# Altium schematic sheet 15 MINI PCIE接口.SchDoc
size 297 x 209 mm
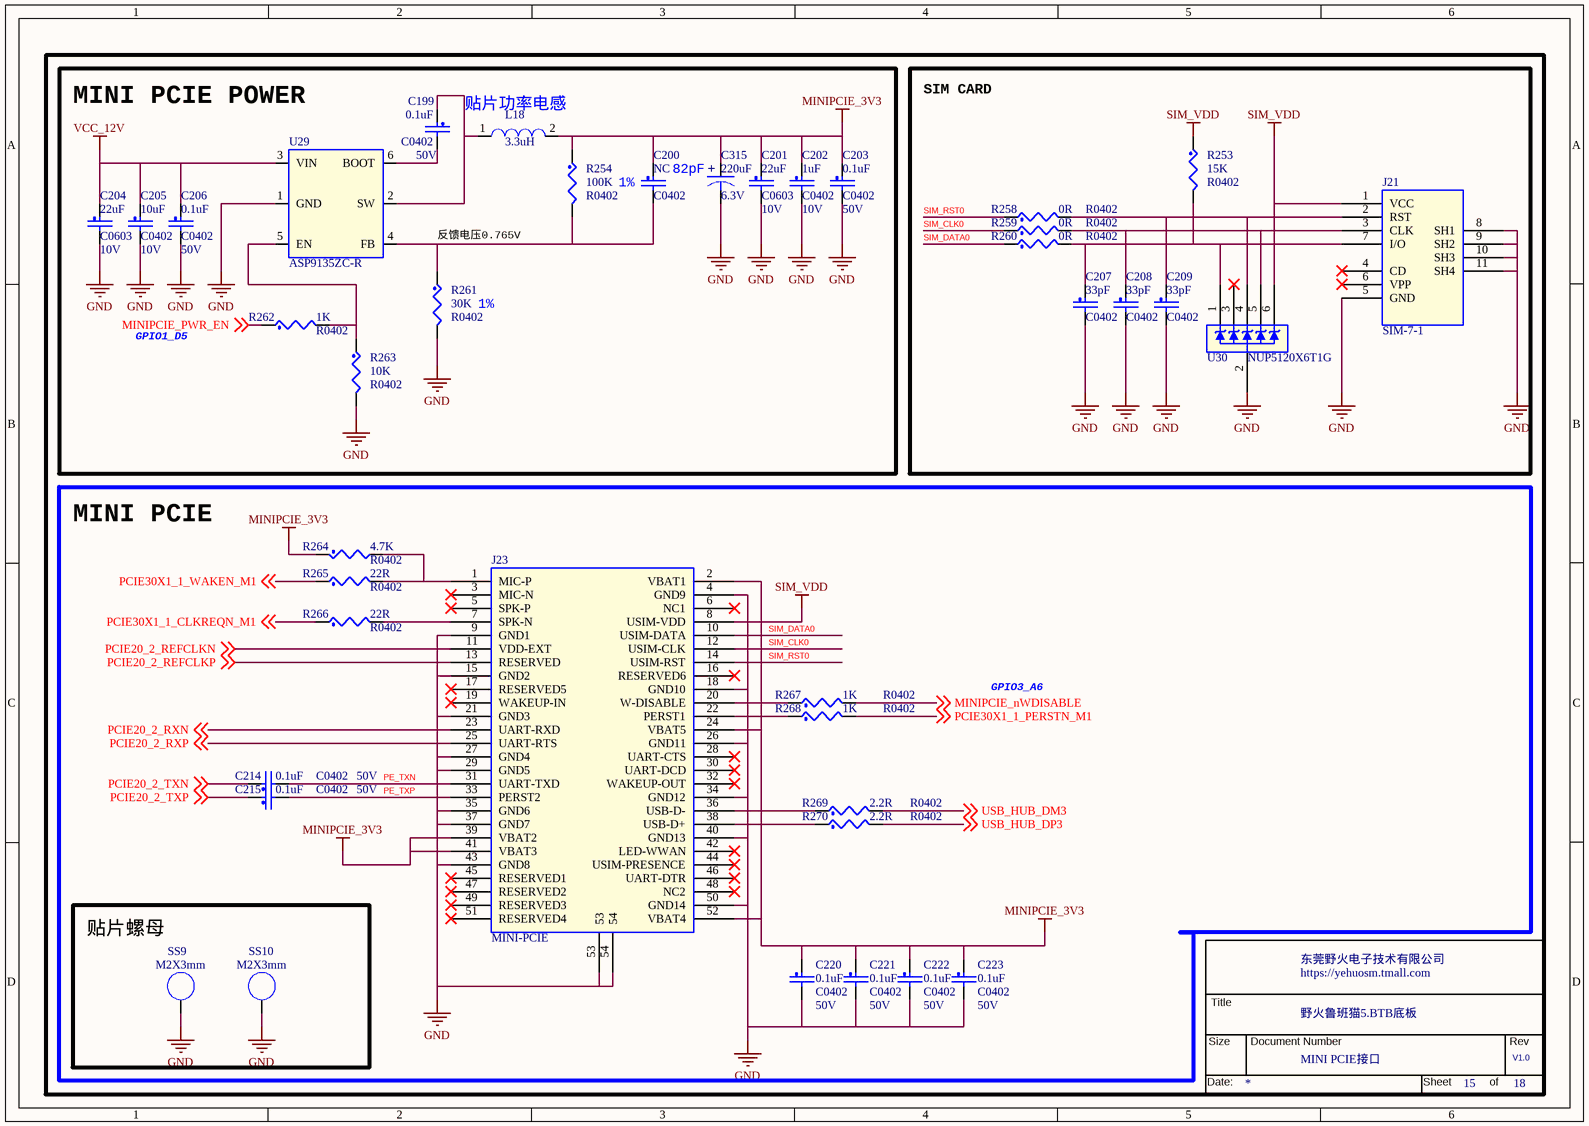
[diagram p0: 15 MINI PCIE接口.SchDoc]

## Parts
*  Doc: MINI PCIE接口  RevCode: V1.0  Title: 野火鲁班猫5.BTB底板  OrgName: 东莞野火电子技术有限公司  Page Number: 15  Page Count: 18  (hidden comment: TitleBlock_YHSCH)  (graphical)
C199  0.1uF  Voltage: 50V  [C0402]
C200  NC  [C0402]
C201  22uF  Voltage: 10V  [C0603]
C202  1uF  Voltage: 10V  [C0402]
C203  0.1uF  Voltage: 50V  [C0402]
C204  22uF  Voltage: 10V  [C0603]
C205  10uF  Voltage: 10V  [C0402]
C206  0.1uF  Voltage: 50V  [C0402]
C207  33pF  [C0402]
C208  33pF  [C0402]
C209  33pF  [C0402]
C214  0.1uF  Voltage: 50V  [C0402]
C215  0.1uF  Voltage: 50V  [C0402]
C220  0.1uF  Voltage: 50V  [C0402]
C221  0.1uF  Voltage: 50V  [C0402]
C222  0.1uF  Voltage: 50V  [C0402]
C223  0.1uF  Voltage: 50V  [C0402]
C315  220uF  Voltage: 6.3V  [T2012]
J21  SIM-7-1  [nano_sim]
J23  MINI-PCIE  [pcie_52p]
L18  3.3uH  [l4520]
R253  15K  [R0402]
R254  100K  [R0402]
R258  0R  [R0402]
R259  0R  [R0402]
R260  0R  [R0402]
R261  30K  [R0402]
R262  1K  [R0402]
R263  10K  [R0402]
R264  4.7K  [R0402]
R265  22R  [R0402]
R266  22R  [R0402]
R267  1K  [R0402]
R268  1K  [R0402]
R269  2.2R  [R0402]
R270  2.2R  [R0402]
SS9  M2X3mm  [t3r2-5r2_topsmt]
SS10  M2X3mm  [t3r2-5r2_topsmt]
U29  ASP9135ZC-R  [SOT23_6]
U30  NUP5120X6T1G  [SOT563]

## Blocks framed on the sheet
MINI PCIE POWER: C199-C206 C315 L18 R254 R261-R263 U29
SIM CARD: C207-C209 J21 R253 R258-R260 U30
MINI PCIE: C214 C215 C220-C223 J23 R264-R270
贴片螺母: SS9 SS10

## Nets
GND: C201.2 C202.2 C203.2 C204.2 C205.2 C206.2 C207.2 C208.2 C209.2 C220.2 C221.2 C222.2 C223.2 C315.2 J21.5(GND) J21.8(SH1) J21.9(SH2) J21.10(SH3) J21.11(SH4) J23.4(GND9) J23.9(GND1) J23.15(GND2) J23.18(GND10) J23.21(GND3) J23.26(GND11) J23.27(GND4) J23.29(GND5) J23.34(GND12) J23.35(GND6) J23.37(GND7) J23.40(GND13) J23.43(GND8) J23.50(GND14) J23.53 J23.54 R261.2 R263.2 SS9.1(NC_1) SS10.1(NC_1) U29.1(GND) U30.2
MINIPCIE_3V3: C200.1 C201.1 C202.1 C203.1 C220.1 C221.1 C222.1 C223.1 C315.1 J23.2(VBAT1) J23.24(VBAT5) J23.39(VBAT2) J23.41(VBAT3) J23.52(VBAT4) L18.2 R254.1 R264.1
SIM_VDD: J21.1(VCC) J23.8(USIM-VDD) R253.1 U30.6
VCC_12V: C204.1 C205.1 C206.1 U29.3(VIN)
MINIPCIE_nWDISABLE: R267.2 ; off-sheet MINIPCIE_nWDISABLE
MINIPCIE_PWR_EN: R262.1 ; off-sheet MINIPCIE_PWR_EN
PCIE20_2_REFCLKN: J23.11(VDD-EXT) ; off-sheet PCIE20_2_REFCLKN
PCIE20_2_REFCLKP: J23.13(RESERVED) ; off-sheet PCIE20_2_REFCLKP
PCIE20_2_RXN: J23.23(UART-RXD) ; off-sheet PCIE20_2_RXN
PCIE20_2_RXP: J23.25(UART-RTS) ; off-sheet PCIE20_2_RXP
PCIE20_2_TXN: C214.1 ; off-sheet PCIE20_2_TXN
PCIE20_2_TXP: C215.1 ; off-sheet PCIE20_2_TXP
PCIE30X1_1_CLKREQN_M1: R266.1 ; off-sheet PCIE30X1_1_CLKREQN_M1
PCIE30X1_1_PERSTN_M1: R268.2 ; off-sheet PCIE30X1_1_PERSTN_M1
PCIE30X1_1_WAKEN_M1: R265.1 ; off-sheet PCIE30X1_1_WAKEN_M1
PE_TXN: C214.2 J23.31(UART-TXD)
PE_TXP: C215.2 J23.33(PERST2)
SIM_CLK0: J23.12(USIM-CLK) R259.1
SIM_DATA0: J23.10(USIM-DATA) R260.1
SIM_RST0: J23.14(USIM-RST) R258.1
USB_HUB_DM3: R269.2 ; off-sheet USB_HUB_DM3
USB_HUB_DP3: R270.2 ; off-sheet USB_HUB_DP3
NetC199_1: C199.1 L18.1 U29.2(SW)
NetC199_2: C199.2 U29.6(BOOT)
NetC200_2: C200.2 R254.2 R261.1 U29.4(FB)
NetC207_1: C207.1 J21.7(I/O) R253.2 R260.2 U30.1
NetC208_1: C208.1 J21.3(CLK) R259.2 U30.5
NetC209_1: C209.1 J21.2(RST) R258.2 U30.4
NetJ23_1: J23.1(MIC-P) R264.2 R265.2
NetJ23_7: J23.7(SPK-N) R266.2
NetJ23_20: J23.20(W-DISABLE) R267.1
NetJ23_22: J23.22(PERST1) R268.1
NetJ23_36: J23.36(USB-D-) R269.1
NetJ23_38: J23.38(USB-D+) R270.1
NetR262_2: R262.2 R263.1 U29.5(EN)

Not connected (* = marked no-connect by the designer): J21 4(CD)* 6(VPP)*; J23 3(MIC-N)* 5(SPK-P)* 6(NC1)* 16(RESERVED6)* 17(RESERVED5)* 19(WAKEUP-IN)* 28(UART-CTS)* 30(UART-DCD)* 32(WAKEUP-OUT)* 42(LED-WWAN)* 44(USIM-PRESENCE)* 45(RESERVED1)* 46(UART-DTR)* 47(RESERVED2)* 48(NC2)* 49(RESERVED3)* 51(RESERVED4)*; U30 3*

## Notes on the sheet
- 贴片功率电感
- (near C200) 1%
- 82pF
- 反馈电压0.765V
- GPIO1_D5
- (near R261) 1%
- GPIO3_A6

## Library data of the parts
* = TitleBlock_YHSCH: Cage Code: 1
C199 C203 C206 C214 C215 C220-C223 = CAP_NP: CLASS: DISCRETE; 生命周期: 量产; 价格: 0.029826; 规格书: 风华电容.pdf; 类别: 贴片电容0402; 品牌: 风华; 条码: EBF29060118; 规格编号: 0402X104K500NT; 规格: 贴片电容0.1uF 10% 50V X5R 0402
C200 = CAP_NP: CLASS: DISCRETE; 规格: 贴片电容NC 预留; 条码: EBF29060149; 类别: 贴片电容0402
C201 C204 = CAP_NP: CLASS: DISCRETE; 规格: 贴片电容22uF 20% 10V X5R 0603; 规格编号: CL10A226MP8NUNE; 条码: EBF29060163; 品牌: 三星; 类别: 贴片电容0603; 规格书: 三星电容.pdf; 价格: 0.078818; 生命周期: 量产
C202 = CAP_NP: CLASS: DISCRETE; 规格: 贴片电容1uF 10% 10V X5R 0402; 规格编号: 0402X105K100NT; 条码: EBF29060121; 品牌: 风华; 类别: 贴片电容0402; 规格书: 风华电容.pdf; 价格: 0.01191; 生命周期: 量产
C205 = CAP_NP: CLASS: DISCRETE; 生命周期: 量产; 价格: 0.518415; 规格书: 三星电容.pdf; 类别: 贴片电容0402; 品牌: 三星; 条码: EBF29060247; 规格编号: CL05A106MP8NUB8; 规格: 贴片电容10uF 20% 10V X5R 0402
C207 C208 = CAP_NP: Voltage: 50V; CLASS: DISCRETE; 规格: 贴片电容33pF 5% 50V 0402; 规格编号: 0402CG330J500NT; 条码: EBF29060298; 品牌: 风华; 类别: 贴片电容0402; 规格书: 风华电容.pdf; 生命周期: 量产
C209 = CAP_NP: Voltage: 50V; CLASS: DISCRETE; 生命周期: 量产; 规格书: 风华电容.pdf; 类别: 贴片电容0402; 品牌: 风华; 条码: EBF29060298; 规格编号: 0402CG330J500NT; 规格: 贴片电容33pF 5% 50V 0402
C315 = CAP: PCB Footprint: CASE-B_3528; 规格: 贴片电容220uF 20% 6.3V 坦电容 CASE-B_3528; 规格编号: TLJB227M006R0500; 条码: EBF29060264; 品牌: AVX; 类别: 贴片坦电容; 规格书: AVX_贴片坦电容.pdf; 价格: 1.28; 生命周期: 量产
J21 = SIM-7-1: 规格: nano sim卡座; 规格编号: HYC63-SIM07-137; 条码: EBF29040054; 品牌: 华宇创; 类别: SIM卡座连接器; 规格书: 华宇创_NANOSIMPUSH1.37H带CDPIN带柱.pdf; 价格: 1.48; 生命周期: 量产
J23 = MINI-PCIE: 规格: MINI PCIE插座 引脚数：52P; 规格编号: PCIE-52P56H; 条码: EBF29040055; 品牌: 讯普; 类别: 金手指连接器; 规格书: XUNPU(讯普)_52PMINIPCIE插座.pdf; 价格: 1.935; 生命周期: 量产
L18 = IND: CLASS: DISCRETE; 价格: 1.5992; 规格编号: TMPC0402HP-3R3MG-Z02; 规格: 贴片电感3.3uH ±20% 3A 直流电阻69mΩ; 条码: EBF29050040; 品牌: 台庆; 类别: 贴片电感0402; 规格书: 台庆-功率电感.pdf; 生命周期: 量产
R253 = RES: CLASS: DISCRETE; 规格: 贴片电阻15K 1% 1/16W 0402; 规格编号: RI0402L1502FT; 条码: EBF29070222; 品牌: 合科泰; 类别: 贴片电阻0402; 规格书: 合科泰-RI系列电阻.pdf; 生命周期: 量产
R254 = RES: CLASS: DISCRETE; 生命周期: 量产; 规格书: 合科泰-RI系列电阻.pdf; 类别: 贴片电阻0402; 品牌: 合科泰; 条码: EBF29070054; 规格编号: RI0402L1003FT; 规格: 贴片电阻100K 1% 1/16W 0402
R258-R260 = RES: CLASS: DISCRETE; 生命周期: 量产; 规格书: 合科泰-RI系列电阻.pdf; 类别: 贴片电阻0402; 品牌: 合科泰; 条码: EBF29070049; 规格编号: RI0402L000FT; 规格: 贴片电阻0R 1% 1/16W 0402
R261 = RES: CLASS: DISCRETE; 规格: 贴片电阻30K 1% 1/16W 0402; 规格编号: RI0402L3002FT; 条码: EBF29070048; 品牌: 合科泰; 类别: 贴片电阻0402; 规格书: 合科泰-RI系列电阻.pdf; 生命周期: 量产
R262 R267 R268 = RES: CLASS: DISCRETE; 规格: 贴片电阻1K 1% 1/16W 0402; 规格编号: RI0402L1001FT; 条码: EBF29070050; 品牌: 合科泰; 类别: 贴片电阻0402; 规格书: 合科泰-RI系列电阻.pdf; 生命周期: 量产
R263 = RES: CLASS: DISCRETE; 生命周期: 量产; 价格: 0.002773; 规格书: 厚声-无铅厚膜电阻.pdf; 类别: 贴片电阻0402; 品牌: 厚声; 条码: EBF29070046; 规格编号: 0402WGF1002TCE; 规格: 贴片电阻10K 1% 1/16W 0402
R264 = RES: CLASS: DISCRETE; 规格: 贴片电阻4.7K 1% 1/16W 0402; 规格编号: RI0402L4701FT; 条码: EBF29070047; 品牌: 合科泰; 类别: 贴片电阻0402; 规格书: 合科泰-RI系列电阻.pdf; 生命周期: 量产
R265 R266 = RES: CLASS: DISCRETE; 规格: 贴片电阻22R 1% 1/16W 0402; 规格编号: RI0402L22R0FT; 条码: EBF29070181; 品牌: 合科泰; 类别: 贴片电阻0402; 规格书: 合科泰-RI系列电阻.pdf; 生命周期: 量产
R269 R270 = RES: CLASS: DISCRETE; 规格: 贴片电阻2.2R 1% 1/16W 0402; 规格编号: 0402WGF220KTCE; 条码: EBF29070280; 品牌: 厚声; 类别: 贴片电阻0402; 规格书: 厚声-无铅厚膜电阻.pdf; 生命周期: 量产; 价格: 0.003072
SS9 SS10 = SPACER: CLASS: IC; 规格书: 雄和远景_SMTWE2040CTJ.pdf; 生命周期: 量产; 类别: 贴片螺母; 品牌: 雄和远景; 条码: EBF500026; 规格编号: ZIY01-001; 规格: SMT贴片螺母M2 高度3MM 台阶外径：4.5MM 整体高度：4.5MM 焊接孔外径：3MM
U29 = TP6327GS6: 备注: RK3566金手指与BTB底板替换物料; 生命周期: 量产; 规格书: 安森德_ASP9135ZC-R.pdf; 类别: 电源管理-DCDC; 品牌: 安森德; 条码: EBFCIS240710113940; 规格: DC-DC电源芯片 可输出电流 3A 开关工作频率 600kHz 输出类型 ADJ 输入电压范围：4V-18V
U30 = NUP5120-D: 生命周期: 量产; 价格: 0.39; 规格书: 安森美_NUP5120X6T1G.pdf; 类别: 贴片ESD; 品牌: 安森美; 条码: EBF29140034; 规格: 防静电保护ESD二极管 击穿电压6.2V 反向关断电压5V 封装SOT-523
